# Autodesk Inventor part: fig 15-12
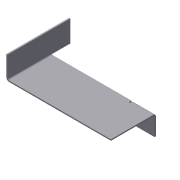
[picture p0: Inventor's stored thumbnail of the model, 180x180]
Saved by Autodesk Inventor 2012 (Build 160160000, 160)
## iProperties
Shininess: 77.0
Angle Display Precision: 2
Document Length Units: 11269
Document Angle Units: 11279
Document Time Units: 11290
Document Mass Units: 11283
Document Length Units Precision: 3
Document Angle Units Precision: 2
Created: 2002-04
Part Number: fig 15-12
Material: Aluminum-6061
Document SubType Name: Sheet Metal
Density: 1 g/cm^3
Sheet Metal Rule: Default
Density: 0.0
Volumn: 0.0
Area: 0.0
PropertySet Name: Model Information
Control State: 0
Master: False
Checked Out: False
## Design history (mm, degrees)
node "Face1"
  sketch "Sketch1"
    geometry: L1 (-49.559, 19.574)-(-49.559, -30.426); L2 (-49.559, -30.426)-(50.441, -30.426); L3 (50.441, -30.426)-(50.441, 19.574); L4 (50.441, 19.574)-(32.941, 19.574); L5 (32.941, 19.574)-(32.941, 4.574); L6 (32.941, 4.574)-(-32.059, 4.574); L7 (-32.059, 4.574)-(-32.059, 19.574); L8 (-32.059, 19.574)-(-49.559, 19.574)
    constraints: 16 end point, 6 parallel, 2 equal length, 1 perpendicular, 1 vertical
    dimensions: "d0" = 100 distance of L1.end L2.end; "d1" = 65 distance of L5.end L6.end; "d2" = 15 distance of L6.end L7.end; "d3" = 50 distance of L1.start L1.end
sketch "Sketch2"
  geometry: L1 (100, 0)-(0, 0) reference; L2 (17.5, 50)-(17.5, 35) reference; L3 (82.5, 50)-(82.5, 0)
  constraints: 2 end point, 1 parallel, 1 point on line
sketch "Sketch3"
  geometry: L1 (81.369, -50)-(0, -50) reference; L2 (17.5, 0)-(17.5, -50)
  constraints: 2 end point, 1 perpendicular, 1 point on line
feature "Fold2" sketch "Sketch3" dims "d8" = 1 (= BendRadius), "d9" = 90 deg, "d10" = 1 (= BendRadius), "d14" = 1 (= BendReliefWidth), "d15" = 0.5 (= BendReliefDepth), "d16" = 2 (= MinimumRemnant), "SeamGap" = 0.01, "Thickness" = 1
sketch "Sketch4"
  geometry: L1 (17.5, 0)-(17.5, -50) reference; L2 (-63.869, -15)-(0, -15) reference; L3 (0, -15)-(17.5, -15)
  constraints: 2 end point, 1 collinear, 1 point on line
feature "Fold3" sketch "Sketch4" dims "d11" = 1 (= BendRadius), "d12" = 90 deg, "d13" = 1, "d17" = 1 (= BendReliefWidth), "d18" = 1, "d19" = 2 (= MinimumRemnant), "SeamGap" = 0.01, "Thickness" = 1
body "Solid1"
face "Plate1" dims "Thickness" = 1
other parameters: "BendRadius" = 1 (= Thickness), "BendReliefWidth" = 1 (= Thickness), "BendReliefDepth" = 0.5 (= 0.5 x Thickness), "CornerReliefSize" = 4 (= 4 x Thickness), "MinimumRemnant" = 2 (= 2 x Thickness), "TransitionRadius" = 1 (= BendRadius), "d4" = 1 (= BendRadius), "JacobiRadiusSize" = 1 (= Thickness), "GapSize" = 1 (= Thickness)
